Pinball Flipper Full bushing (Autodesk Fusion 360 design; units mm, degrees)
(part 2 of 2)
extrude "Extrude37" cut sketch "Flipper Drive Top Labelling" profile of C3 against normal blind 16
extrude "Extrude38" new body sketch "Solenoid Coupling" along normal blind 1.5 and against normal blind 1.5 bodies "Solenoid Coupling 38mm"
extrude "Extrude39" add sketch "Solenoid Coupling" profile of L3 L6 L7 along normal blind 7.6 and against normal blind 7.5
extrude "Extrude40" add sketch "Solenoid Coupling" blind 3 from offset 4.5
extrude "Extrude41" add sketch "Solenoid Coupling" blind -3 from offset -4.5
move "Move17"
move "Move18"
move "Move19"
move_face "MoveFace2"
extrude "Extrude42" new body sketch "Solenoid Coupling" along normal blind 1.5 and against normal blind 1.5 bodies "Solenoid Coupling 41mm", "Solenoid Coupling 42mm", "Solenoid Coupling 40mm", "Solenoid Coupling 43mm", "Solenoid Coupling 39mm"
extrude "Extrude43" new body sketch "Solenoid Coupling" blind 3 from offset 4.5
extrude "Extrude44" new body sketch "Solenoid Coupling" blind -3 from offset -4.5
extrude "Extrude45" add sketch "Solenoid Coupling" profile of L13 L15 L19 L33 L35 L36 L45 L46 L48 L60 L64 L66 L71 L72 L78 along normal blind 5.5 and against normal blind 5.5
chamfer "Chamfer1" distance 2 distance 5
sketch "Coupling base labelling" plane through (0, 0, -31.4) normal (0, 0, 1) x axis (-1, 0, 0)
  dimension "d278" = 6
  dimension "d279" = "'38'"
  dimension "d280" = 6
  dimension "d281" = "'38'"
  dimension "d871" = 6
  dimension "d872" = "'36'"
  dimension "d873" = 6
  dimension "d874" = "'37'"
extrude "Extrude48" add sketch "Flipper Drive" profile of C1 L9 L11 L13 L14 A5 A6 blind 8.8 from offset 11.2
extrude "Extrude49" new body sketch "Flipper Drive" blind 10 from offset 10 bodies "Drive Limiter"
move "Move20"
move "Move21"
extrude "Extrude51" cut sketch "37mm solenoid drill" profile of C1 C2 C3 C4 L6 C5 C6 C7 C8 blind 8 from offset -40
extrude "Extrude52" cut sketch "22mm solenoid drill" profile of C2 C3 C4 C5 C6 C7 C8 C9 C10 blind 8 from offset -39
extrude "Extrude53" cut sketch "22mm solenoid drill" profile of C2 C3 C4 C7 C9 against normal blind 100 taper 0.1
extrude "Extrude46" cut sketch "Coupling base labelling" against normal blind 0.4
sketch "Coupling Labelling" plane through (0, 0, -30.7) normal (0, 0, 1) x axis (-1, 0, 0)
  dimension "d284" = 6
  dimension "d285" = "'39'"
  dimension "d286" = 6
  dimension "d287" = 0 (= "Text2-Text")
  dimension "d288" = 6
  dimension "d289" = "'39'"
  dimension "d290" = 6
  dimension "d291" = "'41'"
  dimension "d292" = 6
  dimension "d293" = "'42'"
  dimension "d294" = 6
  dimension "d295" = "'43'"
extrude "Extrude47" cut sketch "Coupling Labelling" against normal blind 0.4
work_plane "WorkPlane10" AlongDistance 2.7
move "Move22"
move "Move23"
extrude "Extrude54" cut sketch "Flipper" profile of C2 C3 blind -12 from offset -20
move_face "MoveFace3"
sketch "Flipper Dimensions" plane through (0, 0, 0) normal (0, 0, -1) x axis (1, 0, 0)
  dimension "d371" = 6
  dimension "d377" = 6
  dimension "d378" = "'Flipper + 1'"
  dimension "d379" = 6
  dimension "d380" = "'Flipper+0.5'"
extrude "Extrude57" cut sketch "Flipper Dimensions" against normal blind 0.4
move_face "MoveFace4"
move_face "MoveFace5"
move "Move26"
sketch "Flipper Labelling + 1" plane through (0, 0, 0.7) normal (0, 0, 1) x axis (1, 0, 0)
  curve K1
  curve K2
  curve K3
  curve K4
  line L1 (47.766, 7.9632) -> (1.1968, 12.4426)
  line L2 (0, -12.5) -> (47.7564, -7.9642)
  line L3 (47.766, 7.9632) -> (1.1968, 12.4426)
  line L4 (0, -12.5) -> (47.7564, -7.9642)
  line L5 (47.766, 7.9632) -> (1.1968, 12.4426)
  line L6 (0, -12.5) -> (47.7564, -7.9642)
  circle C1 centre (0, 0) radius 6.8
  arc A1 centre (0, 0) radius 12.5 clockwise from (0, -12.5) to (1.1968, 12.4426)
  arc A2 centre (47, 0) radius 8 clockwise from (47.766, 7.9632) to (47.7564, -7.9642)
  circle C2 centre (0, 0) radius 6.8
  arc A3 centre (0, 0) radius 12.5 clockwise from (0, -12.5) to (1.1968, 12.4426)
  arc A4 centre (47, 0) radius 8 clockwise from (47.766, 7.9632) to (47.7564, -7.9642)
  circle C3 centre (0, 0) radius 6.8
  arc A5 centre (0, 0) radius 12.5 clockwise from (0, -12.5) to (1.1968, 12.4426)
  arc A6 centre (47, 0) radius 8 clockwise from (47.766, 7.9632) to (47.7564, -7.9642)
  dimension "d397" Text1-Height = 7
  dimension "d398" Flipper+1 = "'Flipper+1'"
extrude "Extrude64" new body sketch "Bushing" profile of C1 C2 blind -9.8 from offset -0.6 bodies "Bushing + 1"
sketch "Sketch35" plane through (0, 0, 0) normal (0, 1, 0) x axis (1, 0, 0)
  dimension "d412" = 3
  dimension "d413" = "'Bushing+1'"
emboss "Emboss1" sketch "Sketch35" Depth -0.4 Horizontal Distance 0 Vertical Distance 0 Rotation Angle 0
extrude "Extrude65" new body sketch "Washers Upper" profile of C1 C2 blind -0.6 from offset -0.1 bodies "Washer 0.6"
extrude "Extrude66" new body sketch "Solenoid Coupling" along normal blind 1.5 and against normal blind 1.5 bodies "Solenoid Coupling 47mm", "Solenoid Coupling 45mm"
chamfer "Chamfer2" distance 2 distance 4
extrude "Extrude67" add sketch "Solenoid Coupling" profile of L91 L99 L100 L102 L104 L105 L106 L107 L108 L113 L114 L120 along normal blind 5.5 and against normal blind 5.5
extrude "Extrude68" add sketch "Solenoid Coupling" blind -3 from offset -4.5
extrude "Extrude69" add sketch "Solenoid Coupling" blind 3 from offset 4.5
chamfer "Chamfer3" distance 4 distance 2
chamfer "Chamfer4" distance 4 distance 2
sketch "Sketch36" plane through (0, 0, -33.7) normal (0, 0, -1) x axis (1, 0, 0)
  dimension "d451" = 6
  dimension "d452" = "'45'"
  dimension "d453" = 6
  dimension "d454" = "'47'"
extrude "Extrude70" cut sketch "Sketch36" against normal blind 0.4
move "Move27"
sketch "Filpper-Straight" plane through (0, 0, 0) normal (0, 0, 1) x axis (1, 0, 0)
  line L1 (-5.745, 3.7993) -> (5.745, 3.7993)
  line L2 (47.7564, -7.9642) -> (0, -12.5)
  line L3 (-5.745, -3.7993) -> (5.745, -3.7993)
  line L4 (47.766, 7.9632) -> (1.1968, 12.4426)
  line L5 (47.766, 207.9632) -> (1.1968, 212.4426)
  line L6 (-5.745, 196.2007) -> (5.745, 196.2007)
  line L7 (47.7564, 192.0358) -> (0, 187.5)
  line L8 (-5.745, 203.7993) -> (5.745, 203.7993)
  arc A1 centre (47, 0) radius 8 clockwise from (47.766, 7.9632) to (47.7564, -7.9642)
  circle C1 centre (4.3, 0) radius 1.4
  circle C2 centre (0, 0) radius 6.8
  arc A2 centre (0, 0) radius 12.5 clockwise from (2.3532, -12.2765) to (1.1968, 12.4426)
  circle C3 centre (-4.3, 0) radius 1.4
  circle C4 centre (0, 200) radius 6.8
  arc A3 centre (0, 200) radius 12.5 clockwise from (2.3532, 187.7235) to (1.1968, 212.4426)
  circle C5 centre (-4.3, 200) radius 1.4
  arc A4 centre (47, 200) radius 8 clockwise from (47.766, 207.9632) to (47.7564, 192.0358)
  circle C6 centre (4.3, 200) radius 1.4
  point P7 (0, 0)
  point P8 (0, 0)
  point P10 (0, -12.5)
  point P12 (2.3532, -12.2765)
  point P13 (0, 0)
  point P19 (0, 200)
  point P29 (0, 200)
  point P17 (0, 187.5)
  point P28 (2.3532, 187.7235)
  point P21 (0, 200)
  coincident P7 P8
  coincident P10 A2
  tangent A1 L2
  tangent A2 L4
  tangent A1 L4
  coincident P12 L2
  coincident P7 P13
  coincident P19 P29
  coincident P17 A3
  tangent A4 L7
  tangent A3 L5
  tangent L5 A4
  coincident P28 L7
  coincident P21 P29
  dimension "d473" diameter C2 = 13.6
  dimension "d474" diameter C1 = 2.8
  dimension "d475" diameter C3 = 2.8
  dimension "d606" diameter C4 = 13.6
  dimension "d607" diameter C6 = 2.8
  dimension "d608" diameter C5 = 2.8
extrude "Extrude71" new body sketch "Filpper-Straight" profile of C1 C2 L1 C3 L3 blind -31.6 from offset 0.4 bodies "Flipper_Straight"
extrude "Extrude72" cut sketch "Filpper-Straight" profile of C2 L1 L3 blind -19 taper 3 from offset -22.3
extrude "Extrude73" add sketch "Filpper-Straight" profile of A1 C1 C2 A2 L1 C3 L2 L3 L4 blind 25 from offset 0.4
sweep "Sweep3" sketch "Rubber Band profile" TwistAngle 0 TaperAngle 0
extrude "Extrude74" cut sketch "Filpper-Straight" profile of C1 C3 blind -11 from offset -21
extrude "Extrude75" cut sketch "Silicon Chip Logo Flipper" against normal blind 0.4
extrude "Extrude76" new body sketch "Filpper-Straight" profile of A1 C1 C2 A2 L1 C3 L2 L3 L4 blind 25 from offset 0.4 bodies "Flipper Straight + 1"
sweep "Sweep4" sketch "Rubber Band profile" TwistAngle 0 TaperAngle 0
extrude "Extrude77" add sketch "Filpper-Straight" profile of C1 C2 L1 C3 L3 blind -32.6 from offset 0.4
extrude "Extrude78" cut sketch "Filpper-Straight" profile of C2 L1 L3 blind -19 taper 3 from offset -23.3
extrude "Extrude79" cut sketch "Filpper-Straight" profile of C1 C3 blind -19 from offset -22
extrude "Extrude80" cut sketch "Silicon Chip Logo Flipper" against normal blind 0.4
combine "Combine2" bodies "Bushing + 1"
sketch "Sketch38" plane through (0, 0, -31.2) normal (0, 0, -1) x axis (1, 0, 0)
  line L1 (3.473, -19.6962) -> (2.6047, -14.7721)
  line L2 (9.6418, -11.4907) -> (12.8558, -15.3209)
  line L3 (-3.473, 19.6962) -> (-2.6047, 14.7721)
  line L4 (-9.6418, 11.4907) -> (-12.8558, 15.3209)
  line L5 (0.4316, 7.0869) -> (-6.5119, -2.8294)
  line L6 (-0.4316, -7.0869) -> (6.5119, 2.8294)
  line L7 (13.209, 4.0188) -> (9.5966, 1.4894)
  line L8 (13.5885, 3.4768) -> (13.209, 4.0188)
  line L9 (9.9761, 0.9473) -> (13.5885, 3.4768)
  line L10 (10.9209, -0.4021) -> (9.9761, 0.9473)
  line L11 (10.4376, -0.7405) -> (10.9209, -0.4021)
  line L12 (8.1644, 2.5059) -> (10.4376, -0.7405)
  line L13 (8.6478, 2.8444) -> (8.1644, 2.5059)
  line L14 (9.5966, 1.4894) -> (8.6478, 2.8444)
  curve K1 (10.9221, 5.2155) -> (11.2016, 6.4396)
  curve K2 (10.0639, 4.2648) -> (10.9221, 5.2155)
  curve K3 (8.0838, 3.6944) -> (10.0639, 4.2648)
  curve K4 (6.517, 4.7041) -> (8.0838, 3.6944)
  curve K5 (6.072, 5.9164) -> (6.517, 4.7041)
  curve K6 (6.3416, 7.1398) -> (6.072, 5.9164)
  curve K7 (7.2737, 8.1485) -> (6.3416, 7.1398)
  curve K8 (8.5645, 8.6776) -> (7.2737, 8.1485)
  curve K9 (9.8079, 8.4865) -> (8.5645, 8.6776)
  curve K10 (10.7572, 7.669) -> (9.8079, 8.4865)
  curve K11 (11.2016, 6.4396) -> (10.7572, 7.669)
  line L15 (-9.5357, -4.182) -> (-11.6277, -5.6469)
  line L16 (-9.3162, -4.4955) -> (-9.5357, -4.182)
  line L17 (-11.7736, -6.2162) -> (-9.3162, -4.4955)
  line L18 (-12.1164, -5.7268) -> (-11.7736, -6.2162)
  line L19 (-10.7837, -3.9267) -> (-12.1164, -5.7268)
  curve K12 (-10.5021, -3.5547) -> (-10.7837, -3.9267)
  curve K13 (-10.9876, -3.6998) -> (-10.5021, -3.5547)
  line L20 (-13.1094, -4.3086) -> (-10.9876, -3.6998)
  line L21 (-13.4157, -3.8711) -> (-13.1094, -4.3086)
  line L22 (-10.9583, -2.1504) -> (-13.4157, -3.8711)
  line L23 (-10.7388, -2.4638) -> (-10.9583, -2.1504)
  line L24 (-12.7956, -3.904) -> (-10.7388, -2.4638)
  line L25 (-10.2388, -3.1779) -> (-12.7956, -3.904)
  line L26 (-10.0334, -3.4713) -> (-10.2388, -3.1779)
  line L27 (-11.6277, -5.6469) -> (-10.0334, -3.4713)
  line L28 (-9.7284, -5.9583) -> (-9.2708, -5.6378)
  line L29 (-9.2225, -6.6808) -> (-9.7284, -5.9583)
  line L30 (-9.5108, -6.8827) -> (-9.2225, -6.6808)
  line L31 (-10.2414, -5.8428) -> (-9.5108, -6.8827)
  line L32 (-9.3295, -5.2043) -> (-10.2414, -5.8428)
  curve K14 (-8.6958, -5.4975) -> (-9.3295, -5.2043)
  curve K15 (-8.2332, -5.953) -> (-8.6958, -5.4975)
  curve K16 (-7.9275, -6.7196) -> (-8.2332, -5.953)
  curve K17 (-8.0631, -7.4803) -> (-7.9275, -6.7196)
  curve K18 (-8.6129, -8.0901) -> (-8.0631, -7.4803)
  curve K19 (-9.3876, -8.409) -> (-8.6129, -8.0901)
  curve K20 (-10.1517, -8.3007) -> (-9.3876, -8.409)
  curve K21 (-10.7568, -7.7576) -> (-10.1517, -8.3007)
  curve K22 (-11.0079, -7.2152) -> (-10.7568, -7.7576)
  curve K23 (-11.0039, -6.709) -> (-11.0079, -7.2152)
  curve K24 (-10.7319, -6.2412) -> (-11.0039, -6.709)
  line L33 (-10.446, -6.4783) -> (-10.7319, -6.2412)
  curve K25 (-10.6448, -6.8223) -> (-10.446, -6.4783)
  curve K26 (-10.6523, -7.1773) -> (-10.6448, -6.8223)
  curve K27 (-10.4797, -7.5611) -> (-10.6523, -7.1773)
  curve K28 (-10.1419, -7.8991) -> (-10.4797, -7.5611)
  curve K29 (-9.7797, -8.0364) -> (-10.1419, -7.8991)
  curve K30 (-9.428, -8.0213) -> (-9.7797, -8.0364)
  curve K31 (-8.8678, -7.7689) -> (-9.428, -8.0213)
  curve K32 (-8.3972, -7.2708) -> (-8.8678, -7.7689)
  curve K33 (-8.2993, -6.7113) -> (-8.3972, -7.2708)
  curve K34 (-8.5136, -6.1769) -> (-8.2993, -6.7113)
  curve K35 (-8.8836, -5.8215) -> (-8.5136, -6.1769)
  curve K36 (-9.2708, -5.6378) -> (-8.8836, -5.8215)
  line L34 (-6.6506, -8.3024) -> (-8.818, -9.8201)
  line L35 (-6.4229, -8.6276) -> (-6.6506, -8.3024)
  line L36 (-8.5903, -10.1453) -> (-6.4229, -8.6276)
  line L37 (-8.0234, -10.9549) -> (-8.5903, -10.1453)
  line L38 (-8.3134, -11.158) -> (-8.0234, -10.9549)
  line L39 (-9.6773, -9.2101) -> (-8.3134, -11.158)
  line L40 (-9.3873, -9.0071) -> (-9.6773, -9.2101)
  line L41 (-8.818, -9.8201) -> (-9.3873, -9.0071)
  line L42 (8.4474, 10.819) -> (6.7823, 9.6531)
  line L43 (8.827, 10.277) -> (8.4474, 10.819)
  line L44 (4.7312, 7.4091) -> (8.827, 10.277)
  line L45 (3.6494, 8.9541) -> (4.7312, 7.4091)
  curve K37 (3.2522, 9.6045) -> (3.6494, 8.9541)
  curve K38 (3.0895, 10.2442) -> (3.2522, 9.6045)
  curve K39 (3.255, 10.8493) -> (3.0895, 10.2442)
  curve K40 (3.7267, 11.3649) -> (3.255, 10.8493)
  curve K41 (4.8438, 11.6516) -> (3.7267, 11.3649)
  curve K42 (6.0468, 10.7035) -> (4.8438, 11.6516)
  line L46 (6.7823, 9.6531) -> (6.0468, 10.7035)
  arc A1 centre (0, 0) radius 20 clockwise from (12.8558, -15.3209) to (3.473, -19.6962)
  arc A2 centre (0, 0) radius 15 clockwise from (-2.6047, 14.7721) to (9.6418, -11.4907)
  arc A3 centre (0, 0) radius 20 clockwise from (-12.8558, 15.3209) to (-3.473, 19.6962)
  arc A4 centre (0, 0) radius 15 clockwise from (2.6047, -14.7721) to (-9.6418, 11.4907)
  circle C1 centre (-5, 8.6603) radius 5
  arc A5 centre (0, 0) radius 7.1 clockwise from (-0.4316, -7.0869) to (-6.5119, -2.8294)
  arc A6 centre (0, 0) radius 7.1 clockwise from (0.4316, 7.0869) to (6.5119, 2.8294)
combine "Combine1" bodies "Bushing + 1"
extrude "Extrude81" cut sketch "Flipper Drive" profile of C2 C4 C6 C8 along normal blind 20
extrude "Extrude82" cut sketch "Flipper Drive" profile of C2 C4 C6 C8 along normal blind 20
extrude "Extrude85" add sketch "Flipper Drive" profile of L20 L23 L24 L26 A12 A13 C3 C5 A21 blind 3.5 from offset 10
mirror "Mirror6" mirrorStitchTolerance 0.1 bodies "Drive Limiter Mirrored"
extrude "Extrude86" cut sketch "Flipper Drive" profile of L5 L7 L15 L17 L20 L23 L24 L26 A14 A15 A16 C2 C3 C4 C5 C6 C7 C8 C9 along normal blind 3.8
mirror "Mirror7" mirrorStitchTolerance 0.1 bodies "Base and Bushing 9mm deck Mirrored"
extrude "Extrude83" cut sketch "Flipper Drive" profile of L5 L7 L15 L17 L20 L23 L24 L26 A14 A15 A16 C2 C3 C4 C5 C6 C7 C8 C9 along normal blind 3.8
extrude "Extrude84" add sketch "Flipper Drive" profile of L20 L23 L24 L26 A12 A13 C3 C5 A21 blind 3.5 from offset 10
extrude "Extrude87" cut sketch "Flipper Drive Top Labelling" profile of C2 C3 blind 4 from offset -7.8
mirror "Mirror8" mirrorStitchTolerance 0.1 bodies "Flipper Drive Mirrored"
fillet "Fillet6" radius 2
fillet "Fillet7" radius 2
fillet "Fillet8" radius 2
copy_paste_bodies "CopyPasteBodies6"
mirror "Mirror9" mirrorStitchTolerance 0.1 bodies "Base and Bushing 12mm deck Mirrored"
extrude "Extrude88" add of existing geometry blind 3
extrude "Extrude89" add of existing geometry blind 3
extrude "Extrude90" new body sketch "Flipper" + "Filpper-Straight" profile of S1:A1 S1:A2 S1:L1 S1:L2 S1:C1 S1:L4 S1:L3 S1:C2 S1:C3 S2:A1 S2:C1 S2:C2 S2:A2 S2:L1 S2:C3 S2:L2 S2:L3 S2:L4 blind 25 bodies "Flipper + 2"
extrude "Extrude91" add sketch "Filpper-Straight" profile of C1 C2 L1 C3 L3 against normal blind 33.2
extrude "Extrude92" cut sketch "Filpper-Straight" profile of C2 L1 L3 blind -20 taper 3 from offset -24.3
extrude "Extrude93" cut sketch "Filpper-Straight" profile of C1 C3 blind -15 from offset -23
sweep "Sweep5" sketch "Rubber Band profile" TwistAngle 0 TaperAngle 0
fillet "Fillet9" radius 2
extrude "Extrude94" new body sketch "Filpper-Straight" profile of A1 C1 C2 A2 L1 C3 L2 L3 L4 along normal blind 25 bodies "Flipper + 3"
extrude "Extrude95" add sketch "Filpper-Straight" profile of C1 C2 L1 C3 L3 against normal blind 34.2
extrude "Extrude96" cut sketch "Filpper-Straight" profile of C2 L1 L3 blind -20 taper 3 from offset -25.3 (= "0.0 mm - 25.30 mm")
extrude "Extrude97" cut sketch "Filpper-Straight" profile of C1 C3 blind -20 from offset -25.3
sweep "Sweep6" sketch "Rubber Band profile" TwistAngle 0 TaperAngle 0
fillet "Fillet10" radius 2
extrude "Extrude98" new body sketch "Filpper-Straight" profile of A1 C1 C2 A2 L1 C3 L2 L3 L4 along normal blind 25 bodies "Flipper + 4"
extrude "Extrude99" add sketch "Filpper-Straight" profile of C1 C2 L1 C3 L3 against normal blind 35.2
extrude "Extrude100" cut sketch "Filpper-Straight" profile of C2 L1 L3 blind -20 taper 3 from offset -26.3
extrude "Extrude101" cut sketch "Filpper-Straight" profile of C1 C3 blind -20 from offset -26
sweep "Sweep7" sketch "Rubber Band profile" TwistAngle 0 TaperAngle 0
fillet "Fillet11" radius 2
sketch "Sketch39" plane through (0, 0, -0.4) normal (0, 0, -1) x axis (1, 0, 0)
  circle C1 centre (0, 0) radius 7.3
  circle C2 centre (0, 0) radius 13.5
extrude "Extrude102" new body sketch "Bushing" profile of C1 C2 blind -9.6 from offset -0.6 bodies "Double Drive 9mm deck"
sketch "Double Drive Flipper" plane through (0, 0, -10.2) normal (0, 0, -1) x axis (1, 0, 0)
  line L1 (80, 27) -> (-80, 27)
  line L2 (80, -27) -> (80, 27)
  line L3 (-80, -27) -> (80, -27)
  line L4 (-80, 27) -> (-80, -27)
  circle C1 centre (0, 0) radius 7.3
  circle C2 centre (-74, 21) radius 2.25
  circle C3 centre (-74, 21) radius 4
  circle C4 centre (-44, -21) radius 2.25
  circle C5 centre (-44, -21) radius 4
  circle C6 centre (74, -21) radius 2.25
  circle C7 centre (74, -21) radius 4
  circle C8 centre (44, 21) radius 4
  circle C9 centre (44, 21) radius 2.25
  circle C10 centre (-56.5, -14.5) radius 1.8
  circle C11 centre (-71.5, -2.5) radius 1.8
  circle C12 centre (56.5, 14.5) radius 1.8
  circle C13 centre (71.5, 2.5) radius 1.8
  circle C14 centre (-71.5, -2.5) radius 4
  circle C15 centre (-56.5, -14.5) radius 4
  circle C16 centre (56.5, 14.5) radius 4
  circle C17 centre (71.5, 2.5) radius 4
  point P1 (0, 0)
  point P6 (0, 0)
  horizontal L1
  perpendicular L1 L2
  perpendicular L2 L3
  perpendicular L1 L4
  coincident P1 P6
  concentric C2 C3
  concentric C4 C5
  concentric C8 C9
  concentric C6 C7
  concentric C11 C14
  concentric C10 C15
  concentric C12 C16
  concentric C13 C17
  dimension "d739" diameter C2 = 4.5
  dimension "d740" diameter C3 = 8
  dimension "d741" diameter C4 = 4.5
  dimension "d742" diameter C5 = 8
  dimension "d743" diameter C9 = 4.5
  dimension "d744" diameter C8 = 8
  dimension "d745" diameter C6 = 4.5
  dimension "d746" diameter C7 = 8
  dimension "d749" diameter C14 = 8
  dimension "d750" diameter C15 = 8
  dimension "d751" diameter C16 = 8
  dimension "d752" diameter C17 = 8
extrude "Extrude103" add sketch "Double Drive Flipper" profile of L1 L2 L3 L4 C1 along normal blind 10
extrude "Extrude104" new body sketch "Flipper Drive" blind 8.8 from offset 12.2 bodies "Flipper Drive Double"
extrude "Extrude105" add sketch "Flipper Drive Top Labelling" profile of C1 C2 C3 C6 C7 C8 blind 1 from offset 1
extrude "Extrude106" add sketch "Flipper Drive Top Labelling" profile of C2 C3 C6 C7 blind 3.4 from offset 2
extrude "Extrude107" cut sketch "Flipper Drive Top Labelling" profile of C3 C6 along normal blind 10 and against normal blind 10
extrude "Extrude108" cut sketch "Flipper Drive Top Labelling" profile of C2 C3 C6 C7 blind -5 from offset -3.8
extrude "Extrude110" cut sketch "Flipper Drive" profile of A2 L1 L2 L3 A3 A4 L5 L7 L9 L11 L13 L14 L15 L17 L18 L20 L21 L23 L24 L26 blind 8.8 from offset 12.2
extrude "Extrude111" add sketch "Flipper Drive" profile of A2 L1 L2 L3 A3 A4 L5 L7 L9 L11 L13 L14 L15 L17 L63 L64 L65 L66 blind 8.8 taper 3 from offset 12.2
extrude "Extrude112" cut sketch "Flipper Drive Top Labelling" profile of C2 C3 C6 C7 blind -4 from offset -3.8
sketch "Solenoid Coupling Double 41mm" plane through (0, 0, -32.2) normal (0, 0, -1) x axis (1, 0, 0)
  line L1 (40.1052, 4.4601) -> (40.1053, 14.6628)
  line L2 (22, 4.472) -> (16.9937, 4.472)
  line L3 (16.9926, 14.6618) -> (22, 14.6628)
  line L4 (22, 14.6628) -> (40.1053, 14.6628)
  line L5 (22, 14.6628) -> (22, 4.472)
  line L6 (22, 4.472) -> (40.1052, 4.4601)
  line L7 (-9.2901, 14.6544) -> (-0.1612, 14.657)
  line L8 (-9.2901, 14.6544) -> (-10.8159, 11.9867)
  line L9 (16.9926, 14.6618) -> (16.9931, 12.8497)
  line L10 (16.9937, 4.472) -> (16.9931, 12.8497)
  line L11 (0.2287, 4.4708) -> (16.9937, 4.472)
  line L12 (16.9926, 14.6618) -> (-0.1612, 14.657)
  line L13 (-16.9926, -14.6618) -> (-22, -14.6628)
  line L14 (9.2901, -14.6544) -> (10.8159, -11.9867)
  line L15 (-40.1052, -4.4601) -> (-40.1053, -14.6628)
  line L16 (-16.9937, -4.472) -> (-16.9931, -12.8497)
  line L17 (-22, -4.472) -> (-40.1052, -4.4601)
  line L18 (-16.9926, -14.6618) -> (-16.9931, -12.8497)
  line L19 (-22, -14.6628) -> (-40.1053, -14.6628)
  line L20 (-22, -4.472) -> (-16.9937, -4.472)
  line L21 (-16.9926, -14.6618) -> (0.1612, -14.657)
  line L22 (9.2901, -14.6544) -> (0.1612, -14.657)
  line L23 (-0.2287, -4.4708) -> (-16.9937, -4.472)
  line L24 (-22, -14.6628) -> (-22, -4.472)
  arc A1 centre (-5, 8.6603) radius 6.7 clockwise from (0.2287, 4.4708) to (-10.8159, 11.9867)
  circle C1 centre (35.6066, 8.6557) radius 1.9
  circle C2 centre (-5, 8.6603) radius 3.25
  circle C3 centre (5, -8.6603) radius 3
  circle C4 centre (-35.6066, -8.6557) radius 1.9
  arc A2 centre (5, -8.6603) radius 6.7 clockwise from (-0.2287, -4.4708) to (10.8159, -11.9867)
  circle C5 centre (5, -8.6603) radius 3.25
extrude "Extrude113" new body sketch "Solenoid Coupling Double 41mm" profile of L7 L8 L9 A1 C2 L10 L11 L12 blind 3 from offset 0.1 bodies "Solenoid Coupling Double 41mm"
extrude "Extrude114" add sketch "Solenoid Coupling Double 41mm" profile of L2 L3 L5 L9 L10 along normal blind 7.5 and against normal blind 7.5
extrude "Extrude115" add sketch "Solenoid Coupling Double 41mm" profile of L1 L4 L5 L6 C1 blind 3 from offset 4.5
extrude "Extrude116" add sketch "Solenoid Coupling Double 41mm" profile of L1 L4 L5 L6 C1 blind -3 from offset -4.5
fillet "Fillet12" radius 4
sketch "Solenoid 22mm double" plane through (0, 0, -20.2) normal (0, 0, -1) x axis (1, 0, 0)
  line L1 (80, -27) -> (-80, -27)
  line L2 (80, 27) -> (80, -27)
  line L3 (-80, 27) -> (80, 27)
  line L4 (-80, -27) -> (-80, 27)
  line L5 (51.5, 19.5) -> (51.5, -2.5)
  line L6 (77.5, 19.5) -> (51.5, 19.5)
  line L7 (51.5, -2.5) -> (77.5, -2.5)
  line L8 (77.5, -2.5) -> (77.5, 19.5)
  line L9 (-51.5, -19.5) -> (-51.5, 2.5)
  line L10 (-77.5, -19.5) -> (-51.5, -19.5)
  line L11 (-77.5, 2.5) -> (-77.5, -19.5)
  line L12 (-51.5, 2.5) -> (-77.5, 2.5)
  circle C1 centre (0, 0) radius 7.3
  circle C2 centre (71.5, 2.5) radius 1.8
  circle C3 centre (56.5, 14.5) radius 1.8
  circle C4 centre (-56.5, -14.5) radius 1.8
  circle C5 centre (-71.5, -2.5) radius 1.8
  point P7 (77.5, 19.5)
  point P14 (77.5, 19.5)
  point P10 (77.5, 19.5)
  point P16 (-77.5, -19.5)
  point P24 (-77.5, -19.5)
  point P19 (-77.5, -19.5)
  coincident P7 P14
  perpendicular L7 L8
  perpendicular L5 L7
  coincident P7 P10
  perpendicular L6 L8
  coincident P16 P24
  perpendicular L11 L12
  perpendicular L9 L12
  coincident P19 P24
  perpendicular L10 L11
extrude "Extrude117" new body sketch "Solenoid 22mm double" profile of L5 C2 L6 C3 L7 L8 along normal blind 25 bodies "Solenoid 22mm Double"
sketch "Solenoid 22mm Plunger double" plane through (51.5, 0, 0) normal (-1, 0, 0) x axis (0, -1, 0)
  line L1 (-2.5, -20.2) -> (19.5, -20.2)
  line L2 (-2.5, -45.2) -> (-2.5, -20.2)
  line L3 (19.5, -45.2) -> (-2.5, -45.2)
  line L4 (19.5, -20.2) -> (19.5, -45.2)
  line L5 (19.5, -45.2) -> (-2.5, -20.2)
  line L6 (8.5, -32.7) -> (19.5, -20.2)
  circle C1 centre (8.5, -32.7) radius 4.25
  point P3 (-2.5, -20.2)
  point P7 (-2.5, -20.2)
  point P5 (19.5, -45.2)
  point P8 (19.5, -45.2)
  point P2 (19.5, -20.2)
  point P9 (19.5, -20.2)
  point P10 (8.5, -32.7)
  coincident P3 P7
  coincident P5 P8
  coincident P2 P9
  midpoint L5 P10
  dimension "d722" diameter C1 = 8.5
extrude "Extrude118" add sketch "Solenoid 22mm Plunger double" profile of C1 along normal blind 20
extrude "Extrude119" new body sketch "Solenoid 22mm double" profile of L9 L10 C4 C5 L11 L12 along normal blind 25 bodies "Solenoid 22mm Double 2"
sketch "Solenoid 22mm Plunger Double 2" plane through (-51.5, 0, 0) normal (1, 0, 0) x axis (0, 1, 0)
  line L1 (-2.5, -20.2) -> (19.5, -20.2)
  line L2 (-2.5, -45.2) -> (-2.5, -20.2)
  line L3 (19.5, -45.2) -> (-2.5, -45.2)
  line L4 (19.5, -20.2) -> (19.5, -45.2)
  circle C1 centre (8.6603, -32.2) radius 4.25
  point P6 (8.6603, -32.2)
  point P7 (8.6603, -32.2)
  coincident P6 P7
  dimension "d727" diameter C1 = 8.5
extrude "Extrude120" add sketch "Solenoid 22mm Plunger Double 2" profile of C1 along normal blind 20
extrude "Extrude121" new body sketch "Flipper Drive" blind 10 from offset 11 bodies "Drive Limiter Double"
extrude "Extrude122" add sketch "Flipper Drive" blind 3.5 from offset 11
extrude "Extrude123" cut sketch "Double Drive Flipper" profile of C2 C4 C6 C9 along normal blind 20
extrude "Extrude124" cut sketch "Solenoid 22mm double" profile of C2 C3 C4 C5 against normal blind 20
extrude "Extrude125" cut sketch "Double Drive Flipper" profile of C10 C11 C12 C13 C14 C15 C16 C17 along normal blind 6
extrude "Extrude126" cut sketch "Flipper Drive" profile of L5 L7 L15 L17 L20 L23 L24 L26 A14 A15 A16 C2 C3 C4 C5 C6 C7 C8 C9 along normal blind 5
extrude "Extrude127" cut sketch "Flipper Drive" profile of C2 C4 C6 C8 along normal blind 12
mirror "Mirror10" mirrorStitchTolerance 0.1 bodies "Flipper Drive Double Mirrored"
sketch "Flipper 90" plane through (0, 0, 0) normal (0, 0, 1) x axis (1, 0, 0)
  line L1 (3.7993, 5.745) -> (3.7993, -5.745)
  line L2 (-3.7993, 5.745) -> (-3.7993, -5.745)
  line L3 (47.766, 7.9632) -> (1.1968, 12.4426)
  line L4 (47.7564, -7.9642) -> (0, -12.5)
  arc A1 centre (0, 0) radius 12.5 clockwise from (2.3532, -12.2765) to (1.1968, 12.4426)
  circle C1 centre (0, 4.3) radius 1.4
  arc A2 centre (47, 0) radius 8 clockwise from (47.766, 7.9632) to (47.7564, -7.9642)
  circle C2 centre (0, 0) radius 6.8
  circle C3 centre (0, -4.3) radius 1.4
  point P6 (0, 0)
  point P7 (0, 0)
  point P9 (0, -12.5)
  point P11 (2.3532, -12.2765)
  point P12 (0, 0)
  coincident P6 P7
  coincident P9 A1
  tangent A2 L4
  tangent A1 L3
  tangent A2 L3
  coincident P11 L4
  coincident P7 P12
  dimension "d765" diameter C2 = 13.6
  dimension "d766" diameter C3 = 2.8
  dimension "d767" diameter C1 = 2.8
extrude "Extrude128" new body sketch "Flipper 90" along normal blind 25 bodies "Flipper 90"
sweep "Sweep8" sketch "Rubber Band profile" TwistAngle 0 TaperAngle 0
fillet "Fillet13" radius 2
extrude "Extrude129" add sketch "Flipper 90" profile of C1 L1 L2 C2 C3 against normal blind 31.2
extrude "Extrude130" cut sketch "Flipper 90" profile of L1 L2 C2 blind -20 taper 3 from offset -22.3
extrude "Extrude131" cut sketch "Flipper 90" profile of C1 C3 blind -22 from offset -22
extrude "Extrude132" new body sketch "Flipper 90" profile of C1 L1 L2 C2 C3 against normal blind 32.2 bodies "Flipper 90 + 1"
extrude "Extrude133" add sketch "Flipper 90" along normal blind 25
extrude "Extrude134" cut sketch "Flipper 90" profile of L1 L2 C2 blind -20 taper 3 from offset -23.3
extrude "Extrude135" cut sketch "Flipper 90" profile of C1 C3 blind -20 from offset -20
sweep "Sweep9" sketch "Rubber Band profile" TwistAngle 0 TaperAngle 0
fillet "Fillet14" radius 2
extrude "Extrude136" new body sketch "Flipper 90" along normal blind 25 bodies "Flipper 90 + 2"
extrude "Extrude137" add sketch "Flipper 90" profile of C1 L1 L2 C2 C3 against normal blind 33.2
extrude "Extrude138" cut sketch "Flipper 90" profile of L1 L2 C2 blind -20 taper 3 from offset -24.3
extrude "Extrude139" cut sketch "Flipper 90" profile of C1 C3 blind -20 from offset -24.3
sweep "Sweep10" sketch "Rubber Band profile" TwistAngle 0 TaperAngle 0
fillet "Fillet15" radius 2
extrude "Extrude140" new body sketch "Flipper 90" along normal blind 25 bodies "Flipper 90 + 3"
extrude "Extrude141" add sketch "Flipper 90" profile of C1 L1 L2 C2 C3 against normal blind 34.2
extrude "Extrude142" cut sketch "Flipper 90" profile of L1 L2 C2 blind -20 taper 3 from offset -25.3
extrude "Extrude143" cut sketch "Flipper 90" profile of C1 C3 blind -20 from offset -25.3
sweep "Sweep11" sketch "Rubber Band profile" TwistAngle 0 TaperAngle 0
fillet "Fillet16" radius 2
extrude "Extrude144" new body sketch "Flipper 90" along normal blind 25 bodies "Fliper 90 + 4"
extrude "Extrude145" new body sketch "Flipper 90" profile of C1 L1 L2 C2 C3 against normal blind 35.2
combine "Combine3"
extrude "Extrude146" cut sketch "Flipper 90" profile of L1 L2 C2 blind -20 taper 3 from offset -26.3
extrude "Extrude147" cut sketch "Flipper 90" profile of C1 C3 blind -20 from offset -26
sweep "Sweep12" sketch "Rubber Band profile" TwistAngle 0 TaperAngle 0
fillet "Fillet17" radius 2
extrude "Extrude148" new body sketch "Solenoid Coupling" along normal blind 1.5 and against normal blind 1.5 bodies "Solenoid Coupling 37mm"
extrude "Extrude149" cut sketch "Coupling base labelling" blind 0.4 from offset 0.3
extrude "Extrude150" new body sketch "Solenoid Coupling" along normal blind 1.5 and against normal blind 1.5 bodies "Solenoid Coupling 36mm"
extrude "Extrude151" cut sketch "Coupling base labelling" blind 0.4 from offset 0.4
extrude "Extrude152" add sketch "Solenoid Coupling" along normal blind 7.5 and against normal blind 7.5
extrude "Extrude153" add sketch "Solenoid Coupling" along normal blind 7.5 and against normal blind 7.5
extrude "Extrude154" add sketch "Solenoid Coupling" blind 3 from offset 4.5
extrude "Extrude155" add sketch "Solenoid Coupling" blind -3 from offset -4.5
extrude "Extrude156" add sketch "Solenoid Coupling" blind 3 from offset 4.5
extrude "Extrude157" add sketch "Solenoid Coupling" blind -3 from offset -4.5
sketch "Double Drive Flipper Mirrored" plane through (0, 0, -10.2) normal (0, 0, 1) x axis (1, 0, 0)
  line L1 (-80, -27) -> (80, -27)
  line L2 (80, 27) -> (-80, 27)
  line L3 (-80, 27) -> (-80, -27)
  line L4 (80, -27) -> (80, 27)
  line L5 (-80, 27) -> (80, 27)
  line L6 (-80, -27) -> (-80, 27)
  line L7 (80, -27) -> (-80, -27)
  line L8 (80, 27) -> (80, -27)
  circle C1 centre (0, 0) radius 7.3
  circle C2 centre (74, -21) radius 2.25
  circle C3 centre (71.5, 2.5) radius 4
  circle C4 centre (71.5, 2.5) radius 1.8
  circle C5 centre (-74, 21) radius 2.25
  circle C6 centre (-44, -21) radius 4
  circle C7 centre (44, 21) radius 2.25
  circle C8 centre (-44, -21) radius 2.25
  circle C9 centre (44, 21) radius 4
  circle C10 centre (74, -21) radius 4
  circle C11 centre (-74, 21) radius 4
  circle C12 centre (-74, -21) radius 2.25
  circle C13 centre (0, 0) radius 11
  circle C14 centre (-11.3357, -19.6167) radius 1.75
  circle C15 centre (-11.3357, -19.6167) radius 4
  circle C16 centre (22.1977, -3.9798) radius 1.75
  circle C17 centre (22.1977, -3.9798) radius 4
  circle C18 centre (-22.3238, 3.9473) radius 1.75
  circle C19 centre (-22.3238, 3.9473) radius 4
  circle C20 centre (11.2096, 19.5842) radius 1.75
  circle C21 centre (11.2096, 19.5842) radius 4
  circle C22 centre (-71.5, -14.5) radius 1.8
  circle C23 centre (-71.5, -14.5) radius 4
  circle C24 centre (-56.5, -2.5) radius 1.8
  circle C25 centre (-56.5, -2.5) radius 4
  circle C26 centre (71.5, 14.5) radius 4
  circle C27 centre (71.5, 14.5) radius 1.8
  circle C28 centre (56.5, 2.5) radius 1.8
  circle C29 centre (56.5, 2.5) radius 4
  point P5 (0, 0)
  point P7 (0, 0)
  horizontal L2
  perpendicular L2 L4
  perpendicular L1 L4
  perpendicular L2 L3
  coincident P5 P7
  concentric C5 C11
  concentric C6 C8
  concentric C7 C9
  concentric C2 C10
  concentric C3 C4
  concentric C14 C15
  concentric C18 C19
  concentric C16 C17
  concentric C20 C21
  concentric C22 C23
  concentric C24 C25
  concentric C28 C29
  concentric C26 C27
  dimension "d911" diameter C5 = 4.5
  dimension "d912" diameter C11 = 8
  dimension "d913" diameter C8 = 4.5
  dimension "d914" diameter C6 = 8
  dimension "d915" diameter C7 = 4.5
  dimension "d916" diameter C9 = 8
  dimension "d917" diameter C2 = 4.5
  dimension "d918" diameter C10 = 8
  dimension "d922" diameter C3 = 8
  dimension "d923" diameter C14 = 3.5
  dimension "d924" diameter C15 = 8
  dimension "d925" diameter C18 = 3.5
  dimension "d926" diameter C19 = 8
  dimension "d927" diameter C16 = 3.5
  dimension "d928" diameter C17 = 8
  dimension "d929" diameter C20 = 3.5
  dimension "d930" diameter C21 = 8
  dimension "d939" diameter C23 = 8
  dimension "d940" diameter C25 = 8
  dimension "d941" diameter C29 = 8
  dimension "d942" diameter C26 = 8
extrude "Extrude159" new body sketch "Double Drive Flipper Mirrored" against normal blind 10 bodies "Double Drive 9mm Deck Mirrored"
extrude "Extrude160" cut sketch "Double Drive Flipper Mirrored" profile of C22 C23 C24 C25 C26 C27 C28 C29 against normal blind 6
extrude "Extrude161" cut sketch "Double Drive Flipper Mirrored" profile of C14 C15 C16 C17 C18 C19 C20 C21 against normal blind 6
extrude "Extrude162" add sketch "Double Drive Flipper Mirrored" profile of C1 C13 along normal blind 9.6
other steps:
base_feature "Base Feature" bodies "Base and Bushing", "Base and Bushing 12mm deck"
named bodies: "DO NOT USE FLIPPER PROTO", "Washer Upper", "Base and Bushing 9mm deck", "Base Section", "Solenoid 22mm", "Solenoid 37mm", "Flipper Drive", "Washer Lower", "Drive Arm Washer", "Solenoid Coupling 38mm", "Solenoid Coupling 41mm", "Solenoid Coupling 42mm", "Solenoid Coupling 40mm", "Solenoid Coupling 43mm", "Solenoid Coupling 39mm", "Bushing + 1", "Washer 0.6", "Solenoid Coupling 47mm", "Solenoid Coupling 45mm", "Flipper_Straight", "Flipper Straight + 1", "Drive Limiter", "Drive Limiter Mirrored", "Base and Bushing 9mm deck Mirrored", "Flipper Drive Mirrored", "Base and Bushing", "Base and Bushing 12mm deck", "Base and Bushing 12mm deck Mirrored", "Flipper + 2", "Flipper + 3", "Flipper + 4", "Double Drive 9mm deck", "Flipper Drive Double", "Solenoid Coupling Double 41mm", "Solenoid 22mm Double", "Solenoid 22mm Double 2", "Drive Limiter Double", "Flipper Drive Double Mirrored", "Flipper 90", "Flipper 90 + 1", "Flipper 90 + 2", "Flipper 90 + 3", "Fliper 90 + 4", "Solenoid Coupling 37mm", "Solenoid Coupling 36mm", "Double Drive 9mm Deck Mirrored"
